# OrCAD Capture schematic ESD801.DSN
size A; title: ESD801 1-Channel ESD Protection Diode; rev: 1.0; note: Datasheet: SLVSI98
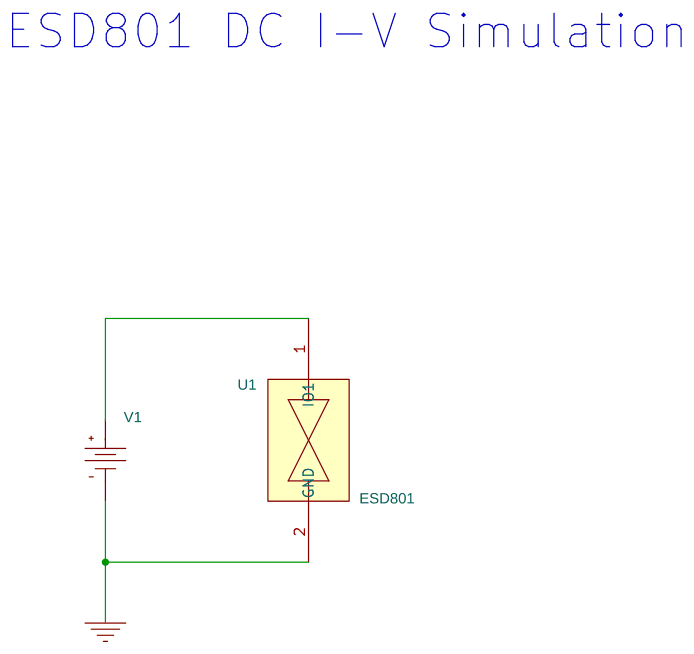
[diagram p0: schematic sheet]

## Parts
U1  ESD801
V1  VDC

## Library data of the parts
U1 = ESD801
V1 = VDC

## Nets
0: U1.2(GND) V1.1(-)
N02917: U1.1(IO1) V1.0(+)

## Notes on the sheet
- ESD801 DC I-V Simulation
